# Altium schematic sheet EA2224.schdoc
size 127 x 101 mm
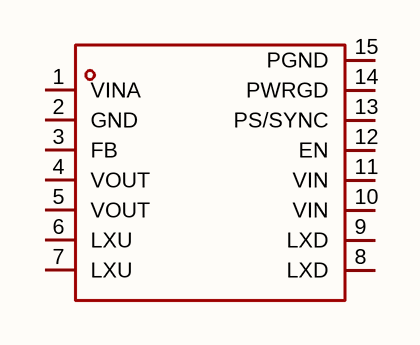
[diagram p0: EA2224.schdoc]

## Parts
U?  ea2224  [VSON-14_L4.0-W3.0-P0.50-BL-EP_TI_DSJ]  (value not drawn)

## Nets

Not connected (* = marked no-connect by the designer): U? 1(VINA) 2(GND) 3(FB) 4(VOUT) 5(VOUT) 6(LXU) 7(LXU) 8(LXD) 9(LXD) 10(VIN) 11(VIN) 12(EN) 13(PS/SYNC) 14(PWRGD) 15(PGND)

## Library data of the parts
U? = ea2224: 功能类型:升降压型;工作电压:2.7V~5.5V;输出电压:2.8V~5.5V;输出电流:3A;输出类型:可调;; Manufacturer: everanalog(申风); AddInBom: yes; ModelId: 36989fe10dd943be902dd02bfe609306; ModelName: VSON-14_L4.0-W3.0-H1.0-P0.50; ModelTransform: 118.8974,158.267,0,90,0,0,0,0,0; Function: 升降压型; Output Current: 3A; Frequency - Switching: 2.2MHz~2.6MHz; Synchronous Rectifier: 是; Number of Outputs: 1; Topology: 降压-升压式; Quiescent Current: 40uA; Switch tube (built-in/external): 内置; Output Type: 可调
